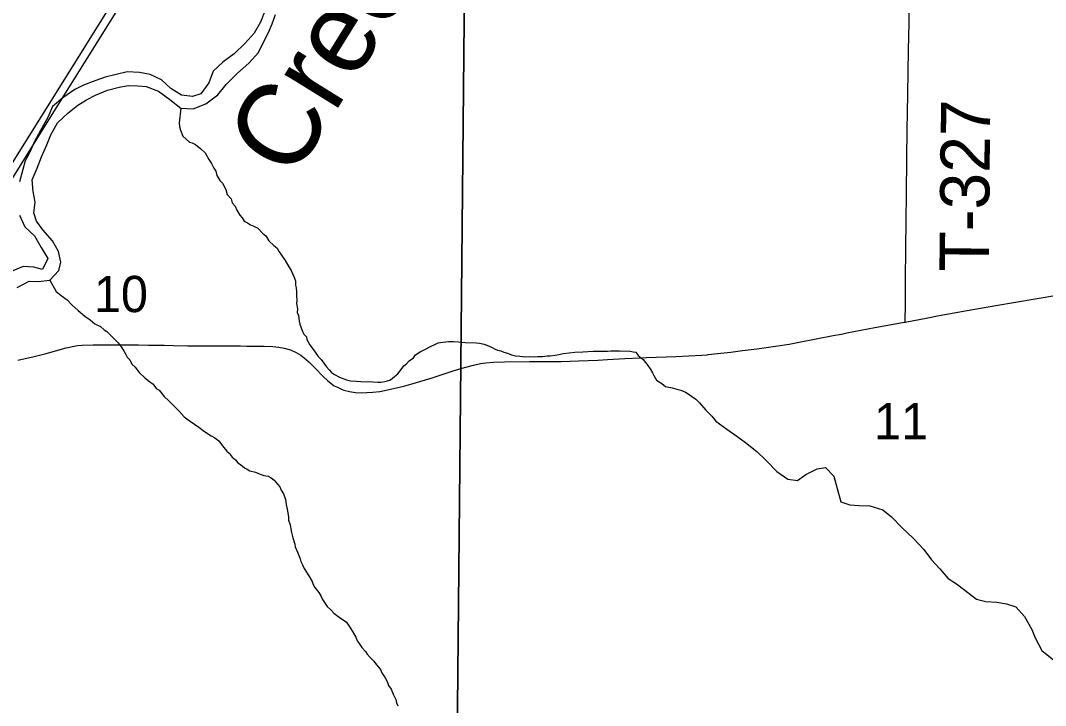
# Model space of a CAD drawing. Extents: x -8.8 to 41.4, y 0 to 34.6.
# Drawn here: x -7.95 to -6.769, y 16.678 to 17.468 of the extents above; entities that cross this region are included whole.
import ezdxf

# ---------------------------------------------------------------- set-up
doc = ezdxf.new("R2010")
doc.units = 0
for name, color, linetype in [('GM_X_Corporation', 7, 'Continuous'), ('GM_X_Corporation_Text', 7, 'Continuous'), ('GM_X_Major_Lake', 7, 'Continuous'), ('GM_X_Minor_River', 7, 'Continuous'), ('GM_X_Rail_Line', 7, 'Continuous'), ('GM_X_Section_Text', 7, 'Continuous'), ('GM_X_State_Route', 7, 'Continuous'), ('GM_X_Township_Road', 7, 'Continuous'), ('GM_X_Township_Text', 7, 'Continuous')]:
    doc.layers.add(name, color=color, linetype=linetype)

msp = doc.modelspace()

# ---------------------------------------------------------------- linework, layer by layer
at = {"layer": 'GM_X_Corporation'}
msp.add_lwpolyline([(-8.37, 16.6231), (-8.3024, 16.7323), (-8.3016, 16.734), (-8.2768, 16.7337), (-8.2489, 16.7335), (-8.2343, 16.7607), (-8.2243, 16.7797), (-8.1899, 16.8441), (-8.1878, 16.8494), (-8.1869, 16.8538), (-8.1794, 16.9318), (-8.1479, 16.9827), (-7.9889, 17.1797), (-7.9797, 17.191), (-8.0175, 17.1927), (-7.9969, 17.2258), (-7.9175, 17.3532), (-7.7632, 17.601), (-7.4937, 18.0343), (-7.4909, 18.0389), (-7.4879, 18.0437), (-7.4285, 18.1393), (-7.2565, 18.415)], dxfattribs=at)
for points in [[(-8.3984, 17.6086), (-7.4378, 17.5869), (-7.4474, 16.5968), (-8.42, 16.6037)], [(-7.4378, 17.5869), (-6.4092, 17.5696), (-6.4339, 16.586), (-7.4474, 16.5968)]]:
    msp.add_lwpolyline(points, close=True, dxfattribs=at)
at = {"layer": 'GM_X_Major_Lake'}
for points in [[(-7.954, 17.16), (-7.9402, 17.1672), (-7.9299, 17.1669), (-7.9162, 17.1683), (-7.906, 17.1794), (-7.9035, 17.1892), (-7.9065, 17.2014), (-7.9133, 17.2138), (-7.9243, 17.2263), (-7.9316, 17.2364), (-7.9347, 17.246), (-7.9332, 17.2585), (-7.9355, 17.2707), (-7.9366, 17.284), (-7.9308, 17.2975), (-7.9259, 17.3106), (-7.9198, 17.3245), (-7.9152, 17.3361), (-7.9076, 17.35), (-7.8955, 17.361), (-7.8842, 17.3701), (-7.8742, 17.3763), (-7.8638, 17.3816), (-7.8499, 17.3877), (-7.8365, 17.3911), (-7.8262, 17.393), (-7.8149, 17.3927), (-7.8051, 17.3916), (-7.7912, 17.3862), (-7.7782, 17.3767), (-7.7652, 17.3668), (-7.7512, 17.366), (-7.7366, 17.3716), (-7.7227, 17.3822), (-7.7132, 17.3941), (-7.6999, 17.407), (-7.687, 17.4187), (-7.676, 17.4309), (-7.67, 17.4429), (-7.6643, 17.4541), (-7.6602, 17.4642), (-7.6561, 17.4747)], [(-7.6693, 17.4767), (-7.6734, 17.4661), (-7.681, 17.4531), (-7.6912, 17.4416), (-7.7038, 17.4295), (-7.7169, 17.42), (-7.7279, 17.4093), (-7.7332, 17.3958), (-7.7424, 17.3832), (-7.7519, 17.3801), (-7.7644, 17.3816), (-7.777, 17.3896), (-7.7877, 17.3994), (-7.8005, 17.4055), (-7.8129, 17.4078), (-7.8273, 17.4086), (-7.8525, 17.4026), (-7.8632, 17.3987), (-7.8774, 17.3934), (-7.8875, 17.3884), (-7.9014, 17.3786), (-7.9131, 17.3687), (-7.9188, 17.356), (-7.9272, 17.3411), (-7.9341, 17.3284), (-7.9394, 17.316), (-7.9446, 17.3059), (-7.9476, 17.2961), (-7.9514, 17.2818)], [(-7.9511, 17.2434), (-7.9451, 17.23), (-7.934, 17.2194), (-7.9261, 17.2062), (-7.9185, 17.1935), (-7.9246, 17.1807), (-7.9347, 17.1833), (-7.9472, 17.1841), (-7.9591, 17.1791)]]:
    msp.add_lwpolyline(points, dxfattribs=at)
at = {"layer": 'GM_X_Minor_River'}
for points in [[(-7.7652, 17.3668), (-7.7672, 17.3497), (-7.7669, 17.3455), (-7.7659, 17.3413), (-7.7631, 17.3343), (-7.7591, 17.3311), (-7.7554, 17.3276), (-7.7524, 17.3267), (-7.7483, 17.3247), (-7.7423, 17.3199), (-7.7372, 17.3152), (-7.7329, 17.3074), (-7.73, 17.3028), (-7.7275, 17.2974), (-7.725, 17.2942), (-7.7237, 17.2893), (-7.7204, 17.2834), (-7.7175, 17.2803), (-7.7136, 17.2729), (-7.7119, 17.2672), (-7.7075, 17.2621), (-7.7061, 17.2575), (-7.7029, 17.2536), (-7.7007, 17.2493), (-7.6975, 17.2435), (-7.6946, 17.2404), (-7.6924, 17.2365), (-7.6887, 17.2345), (-7.685, 17.2321), (-7.6812, 17.2308), (-7.6767, 17.2283), (-7.6713, 17.2225), (-7.6672, 17.2197), (-7.6639, 17.2138), (-7.6581, 17.2083), (-7.6544, 17.2052), (-7.6522, 17.2009), (-7.6493, 17.1974), (-7.645, 17.1911), (-7.6407, 17.1838), (-7.6382, 17.1795), (-7.635, 17.1726), (-7.6333, 17.1676), (-7.6331, 17.1626), (-7.6324, 17.1596), (-7.6322, 17.1554), (-7.632, 17.1504), (-7.6318, 17.1451), (-7.6319, 17.1413), (-7.631, 17.1352), (-7.6311, 17.131), (-7.6297, 17.1275), (-7.6288, 17.1211), (-7.6282, 17.1176), (-7.6251, 17.1091), (-7.6236, 17.1061), (-7.6207, 17.1029), (-7.6201, 17.0998), (-7.6165, 17.094), (-7.6107, 17.0855), (-7.6071, 17.0804), (-7.6038, 17.0769), (-7.6005, 17.0726), (-7.5976, 17.0683), (-7.5943, 17.0651), (-7.5917, 17.062), (-7.5884, 17.0596), (-7.5824, 17.0567), (-7.5745, 17.0534), (-7.57, 17.0521), (-7.5628, 17.0519), (-7.5579, 17.0517), (-7.5511, 17.0511), (-7.548, 17.0514), (-7.5442, 17.0512), (-7.5385, 17.0506), (-7.5347, 17.0509), (-7.5301, 17.0515), (-7.5271, 17.0522), (-7.5236, 17.0535), (-7.5193, 17.0572), (-7.5154, 17.0605), (-7.5102, 17.0668), (-7.5082, 17.0697), (-7.5051, 17.0719), (-7.5023, 17.0752), (-7.4972, 17.0788), (-7.4948, 17.0822), (-7.4894, 17.0858), (-7.484, 17.0883), (-7.4777, 17.0918), (-7.4719, 17.0947), (-7.4689, 17.0961), (-7.4635, 17.0967), (-7.4601, 17.0973), (-7.457, 17.0976), (-7.4513, 17.0978), (-7.4452, 17.0972), (-7.4377, 17.0965)], [(-7.9162, 17.1683), (-7.909, 17.1555), (-7.9034, 17.1508), (-7.8964, 17.1456), (-7.8909, 17.1401), (-7.8835, 17.1334), (-7.8758, 17.127), (-7.8698, 17.1226), (-7.8643, 17.1179), (-7.8579, 17.115), (-7.8535, 17.111), (-7.8505, 17.109), (-7.8469, 17.1055), (-7.8428, 17.1015), (-7.8377, 17.096), (-7.8341, 17.0914), (-7.8308, 17.0863), (-7.8287, 17.0828), (-7.8272, 17.0797), (-7.8243, 17.0766), (-7.8218, 17.0716), (-7.8181, 17.068), (-7.8134, 17.0618), (-7.8068, 17.0558), (-7.8016, 17.0515), (-7.7972, 17.0483), (-7.7939, 17.0436), (-7.7902, 17.0416), (-7.7844, 17.0341), (-7.7792, 17.0294), (-7.7726, 17.0227), (-7.7671, 17.0172), (-7.7616, 17.0109), (-7.7568, 17.0074), (-7.7497, 17.0025), (-7.7445, 16.9989), (-7.7379, 16.9938), (-7.7304, 16.989), (-7.726, 16.9865), (-7.7215, 16.9829), (-7.7186, 16.9787), (-7.7157, 16.9755), (-7.7124, 16.9712), (-7.7095, 16.9688), (-7.7062, 16.9642), (-7.7025, 16.961), (-7.6996, 16.9579), (-7.6966, 16.9559), (-7.6918, 16.9519), (-7.6888, 16.9506), (-7.6859, 16.9486), (-7.6794, 16.9469), (-7.6738, 16.9448), (-7.6697, 16.9431), (-7.6648, 16.9422), (-7.6614, 16.9406), (-7.6577, 16.9378), (-7.6541, 16.9331), (-7.6511, 16.93), (-7.6498, 16.9261), (-7.6472, 16.9218), (-7.6448, 16.9153), (-7.6439, 16.9096), (-7.6429, 16.9042), (-7.6413, 16.8954), (-7.6411, 16.8916), (-7.6394, 16.8862), (-7.6384, 16.8816), (-7.6378, 16.8774), (-7.6361, 16.8713), (-7.6341, 16.864), (-7.6334, 16.8609), (-7.631, 16.8548), (-7.6278, 16.8471), (-7.6272, 16.844), (-7.625, 16.8401), (-7.6233, 16.8359), (-7.6204, 16.8316), (-7.6179, 16.8273), (-7.6139, 16.8208), (-7.6129, 16.8173), (-7.6108, 16.8138), (-7.6064, 16.8083), (-7.6039, 16.8044), (-7.6021, 16.8002), (-7.5996, 16.7967), (-7.5967, 16.792), (-7.5926, 16.7881), (-7.589, 16.7842), (-7.5845, 16.781), (-7.579, 16.777), (-7.5749, 16.7742), (-7.5712, 16.7695), (-7.5677, 16.7633), (-7.5637, 16.7567), (-7.5623, 16.7525), (-7.5598, 16.7493), (-7.5569, 16.7447), (-7.5525, 16.7403), (-7.5507, 16.7369)], [(-7.4377, 17.0965), (-7.4251, 17.0961), (-7.421, 17.0956), (-7.4157, 17.0946), (-7.4127, 17.0934), (-7.4074, 17.0913), (-7.4033, 17.0889), (-7.4003, 17.0876), (-7.3966, 17.0867), (-7.3932, 17.0855), (-7.389, 17.0842), (-7.3842, 17.0821), (-7.3796, 17.0812), (-7.3747, 17.0807), (-7.3717, 17.0802), (-7.3686, 17.0801), (-7.3641, 17.0803), (-7.3576, 17.0801), (-7.3542, 17.0803), (-7.3485, 17.0805), (-7.3431, 17.0811), (-7.3397, 17.0813), (-7.334, 17.0819), (-7.3298, 17.0825), (-7.3244, 17.0838), (-7.3179, 17.0844), (-7.3114, 17.0853), (-7.3019, 17.0857), (-7.2901, 17.0864), (-7.2798, 17.0865), (-7.2737, 17.0866), (-7.2699, 17.0869), (-7.2657, 17.0867), (-7.26, 17.0869), (-7.2475, 17.0865), (-7.2441, 17.0856), (-7.2411, 17.0855), (-7.2382, 17.0816), (-7.2326, 17.0768), (-7.2272, 17.0698), (-7.2243, 17.0663), (-7.2218, 17.0616), (-7.2203, 17.0585), (-7.2171, 17.0531), (-7.2112, 17.0491), (-7.2067, 17.0459), (-7.203, 17.045), (-7.1992, 17.0441), (-7.1939, 17.0428), (-7.189, 17.0415), (-7.1838, 17.0394), (-7.1797, 17.0366), (-7.1767, 17.0346), (-7.1719, 17.031), (-7.1678, 17.0271), (-7.1605, 17.0185), (-7.1572, 17.0153), (-7.1536, 17.0114)], [(-7.1536, 17.0114), (-7.1489, 17.0059), (-7.1362, 16.9965), (-7.1247, 16.9883), (-7.1146, 16.9812), (-7.1016, 16.9706), (-7.0912, 16.9609), (-7.0786, 16.9477), (-7.066, 16.9387), (-7.0546, 16.9372), (-7.045, 16.9442), (-7.0319, 16.9507), (-7.0224, 16.9524), (-7.0128, 16.9423), (-7.009, 16.9282), (-7.0048, 16.9129), (-6.9943, 16.9092), (-6.9837, 16.9086), (-6.9712, 16.9083), (-6.9565, 16.9034), (-6.9464, 16.8955), (-6.9346, 16.8831), (-6.9209, 16.8706), (-6.9091, 16.8578), (-6.9003, 16.8458), (-6.8907, 16.8354), (-6.8811, 16.8245), (-6.8714, 16.8182), (-6.8617, 16.8108), (-6.8483, 16.8006), (-6.8377, 16.7977), (-6.8249, 16.797), (-6.8139, 16.7952), (-6.803, 16.7915), (-6.793, 16.7806), (-6.7847, 16.7656), (-6.7808, 16.7557), (-6.7732, 16.7411), (-6.7594, 16.7301)], [(-7.5507, 16.7369), (-7.547, 16.7333), (-7.543, 16.729), (-7.5397, 16.7247), (-7.5354, 16.7192), (-7.5336, 16.7154), (-7.53, 16.7099), (-7.5275, 16.7056), (-7.5261, 16.701), (-7.5229, 16.6967), (-7.5208, 16.691), (-7.519, 16.6879), (-7.5176, 16.6848), (-7.517, 16.681), (-7.5152, 16.6775)]]:
    msp.add_lwpolyline(points, dxfattribs=at)
at = {"layer": 'GM_X_Rail_Line'}
msp.add_lwpolyline([(-8.2031, 16.904), (-8.1762, 16.9546), (-7.9782, 17.2741), (-7.667, 17.7722), (-7.4314, 18.1516), (-7.3763, 18.2398), (-7.3396, 18.2917)], dxfattribs=at)
at = {"layer": 'GM_X_State_Route'}
msp.add_lwpolyline([(-7.9531, 17.0761), (-7.9344, 17.0805), (-7.9206, 17.084), (-7.8973, 17.0902), (-7.8882, 17.0923), (-7.8845, 17.0929), (-7.8795, 17.0935), (-7.8664, 17.094), (-7.8533, 17.094), (-7.844, 17.094), (-7.8347, 17.0939), (-7.826, 17.0939), (-7.8198, 17.0938), (-7.8142, 17.0938), (-7.8025, 17.0936), (-7.7932, 17.0935), (-7.7845, 17.0934), (-7.7739, 17.0932), (-7.7572, 17.0928), (-7.746, 17.0927), (-7.7324, 17.0927), (-7.7138, 17.0927), (-7.7052, 17.0926), (-7.6965, 17.0925), (-7.6891, 17.0924), (-7.6692, 17.0923), (-7.6592, 17.0918), (-7.6524, 17.0912), (-7.6462, 17.0901), (-7.6389, 17.0879), (-7.6326, 17.085), (-7.6272, 17.0818), (-7.6232, 17.0788), (-7.618, 17.0742), (-7.6109, 17.0671), (-7.6013, 17.0571), (-7.5958, 17.0521), (-7.5907, 17.048), (-7.5887, 17.0466), (-7.5848, 17.0449), (-7.5825, 17.044), (-7.5793, 17.0423), (-7.5776, 17.0416), (-7.5711, 17.0401), (-7.5639, 17.039), (-7.5577, 17.0386), (-7.551, 17.0387), (-7.5442, 17.0392), (-7.5362, 17.0401), (-7.5271, 17.0419), (-7.5084, 17.0462), (-7.4977, 17.0492), (-7.4757, 17.0559), (-7.4515, 17.0638), (-7.4384, 17.0678), (-7.4281, 17.0705), (-7.4202, 17.0722), (-7.414, 17.073), (-7.4052, 17.0737), (-7.3922, 17.0742), (-7.3636, 17.0744), (-7.3449, 17.0744), (-7.3269, 17.0747), (-7.3071, 17.0752), (-7.2848, 17.0761), (-7.2736, 17.0768), (-7.2537, 17.078), (-7.2358, 17.0788), (-7.2289, 17.0793), (-7.1948, 17.0805), (-7.165, 17.0819), (-7.1588, 17.0824), (-7.1576, 17.0826), (-7.1539, 17.083), (-7.1508, 17.0834), (-7.1317, 17.0855), (-7.1182, 17.0872), (-7.1016, 17.0891), (-7.0801, 17.0921), (-7.0642, 17.0947), (-7.0526, 17.0967), (-7.0332, 17.1008), (-7.0136, 17.1045), (-7.0039, 17.1063), (-6.9978, 17.1076), (-6.9654, 17.1137), (-6.9337, 17.1195), (-6.9306, 17.1201), (-6.9044, 17.125), (-6.8916, 17.1275), (-6.8591, 17.1333), (-6.8261, 17.1392), (-6.7808, 17.147), (-6.7263, 17.1562)], dxfattribs=at)
at = {"layer": 'GM_X_Township_Road'}
msp.add_lwpolyline([(-6.9306, 17.1201), (-6.9304, 17.1419), (-6.9303, 17.1587), (-6.9301, 17.1803), (-6.93, 17.1934), (-6.9299, 17.2058), (-6.9295, 17.2362), (-6.9291, 17.2684), (-6.9286, 17.3081), (-6.9282, 17.3423), (-6.9279, 17.3615), (-6.9276, 17.3833), (-6.9267, 17.4336), (-6.9262, 17.4652), (-6.9257, 17.4931)], dxfattribs=at)

# ---------------------------------------------------------------- texts
at = {"layer": 'GM_X_Corporation_Text'}
msp.add_text('Creek', height=0.09467, rotation=58.1724, dxfattribs=at).set_placement((-7.6369, 17.2821))
at = {"layer": 'GM_X_Section_Text'}
msp.add_text('T-327', height=0.05682, rotation=89.4383, dxfattribs=at).set_placement((-6.8344, 17.178))
at = {"layer": 'GM_X_Township_Text'}
for s, p in [('10', (-7.8655, 17.1315)), ('11', (-6.9664, 16.9848))]:
    msp.add_text(s, height=0.04186, rotation=0, dxfattribs=at).set_placement(p)

doc.saveas('drawing.dxf')
